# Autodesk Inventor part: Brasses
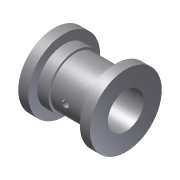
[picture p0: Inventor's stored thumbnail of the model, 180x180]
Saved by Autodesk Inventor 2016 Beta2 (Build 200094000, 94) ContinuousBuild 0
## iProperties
Created: 2009-04
Part Number: Brasses
Document SubType Name: Modeling
Designer: Sham
Density: 1 g/cm^3
Material: Generic
Appearance: Default
Author: Sham
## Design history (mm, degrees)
sketch "Sketch1"
  geometry: L1 (0, 32)-(9, 32); L2 (0, 16)-(64, 16); L3 (64, 32)-(55, 32); L4 (55, 32)-(55, 24); L5 (55, 24)-(47, 24); L6 (19, 22)-(47, 22); L7 (47, 24)-(47, 22); L8 (19, 22)-(19, 24); L9 (19, 24)-(9, 24); L10 (9, 24)-(9, 32); L11 (0, 32)-(0, 16); L12 (64, 32)-(64, 16); L13 (-12.8, 0)-(76.8, 0) reference; 1 further point
  constraints: 24 end point, 7 parallel, 4 perpendicular, 1 collinear, 1 horizontal, 1 vertical alignment, 1 other
  dimensions: "d0" = 9 distance of L1.start L1.end; "d2" = 16 distance from line of L2 point (0, 0); "d3" = 64 distance of L2.start L2.end; "d4" = 24 distance from line of point (0, 0) L5; "d5" = 28 distance of L6.start L6.end; "d6" = 22 distance from line of point (0, 0) L6; "d7" = 8 distance of L4.end L5.end
revolve "Revolution1" sketch "Sketch1" stored, may be unused: angle "d8" = 90 deg
workplane "Work Plane1"
sketch "Sketch2"
  geometry: C1 r 4 at (-32, 0)
  constraints: 1 centre point
  dimensions: "d10" = 8 diameter of C1
extrude "Extrusion1" join sketch "Sketch2" stored distance "d11" = 10; taper "d12" = 0 deg
sketch "Sketch3"
  geometry: C1 r 4 at (0, 0) reference; C2 r 3 at (0, 0)
  constraints: 1 centre point, 1 coincident
  dimensions: "d13" = 6 diameter of C2
extrude "Extrusion2" cut sketch "Sketch3" stored distance "d14" = 10; taper "d15" = 0 deg
body "Solid1"
